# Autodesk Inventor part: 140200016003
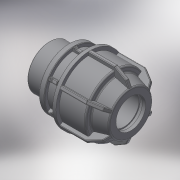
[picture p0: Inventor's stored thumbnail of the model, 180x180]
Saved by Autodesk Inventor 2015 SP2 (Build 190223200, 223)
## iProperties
Created: 2017-08
Part Number: 140200016003
Material: Generic
Description: PLASSON L.14 MALE ADAPTOR (SILVER) 16-3/8''
Document SubType Name: Modeling
Designer: KIM
Density: 1 g/cm^3
Appearance: Default
Author: KIM
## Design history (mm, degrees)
derived "140200.ipt"
feature "Solid1::140200.ipt"
tag "TaggingFeature1"
body "Solid1"
other parameters: "d1" = 16, "d2" = 59, "d4" = 10 deg, "d5" = 38.94, "d6" = 12.8502, "d10" = 32, "d16" = 16.32, "d17" = 2.95, "d18" = 73, "d19" = 3.9, "d21" = 3.9, "d22" = 19.9944, "d24" = 2.95, "d25" = 28.8, "d26" = 24, "d27" = 2.95, "d28" = 135 deg, "d29" = 1.77, "d31" = 0.8, "d44" = 0.32, "d45" = 0.48, "d46" = 160 deg, "d49" = 1.6, "d50" = 0, "d51" = 0.96, "d52" = 0.64, "d53" = 45 deg, "d54" = 21, "d55" = 8.4, "d56" = 1.6, "d57" = 0, "d58" = 0.48, "d59" = 0.32, "d61" = 360 deg, "d63" = 16.662, "d64" = 12.8, "d65" = 13, "d66" = 22.4937, "d_" = 16, "R_" = 16.662, "E_" = 32, "H_" = 73, "l_" = 59, "l_2" = 13
